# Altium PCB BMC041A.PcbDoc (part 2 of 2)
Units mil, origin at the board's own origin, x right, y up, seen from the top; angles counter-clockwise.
Board outline 3850 x 3650 mil, 6 copper layers (Top Layer, MidLayer1, MidLayer2, MidLayer3, MidLayer4, Bottom Layer), stack 62.8 mil thick; 106 components, 43 nets, 241 pads, 352 vias.
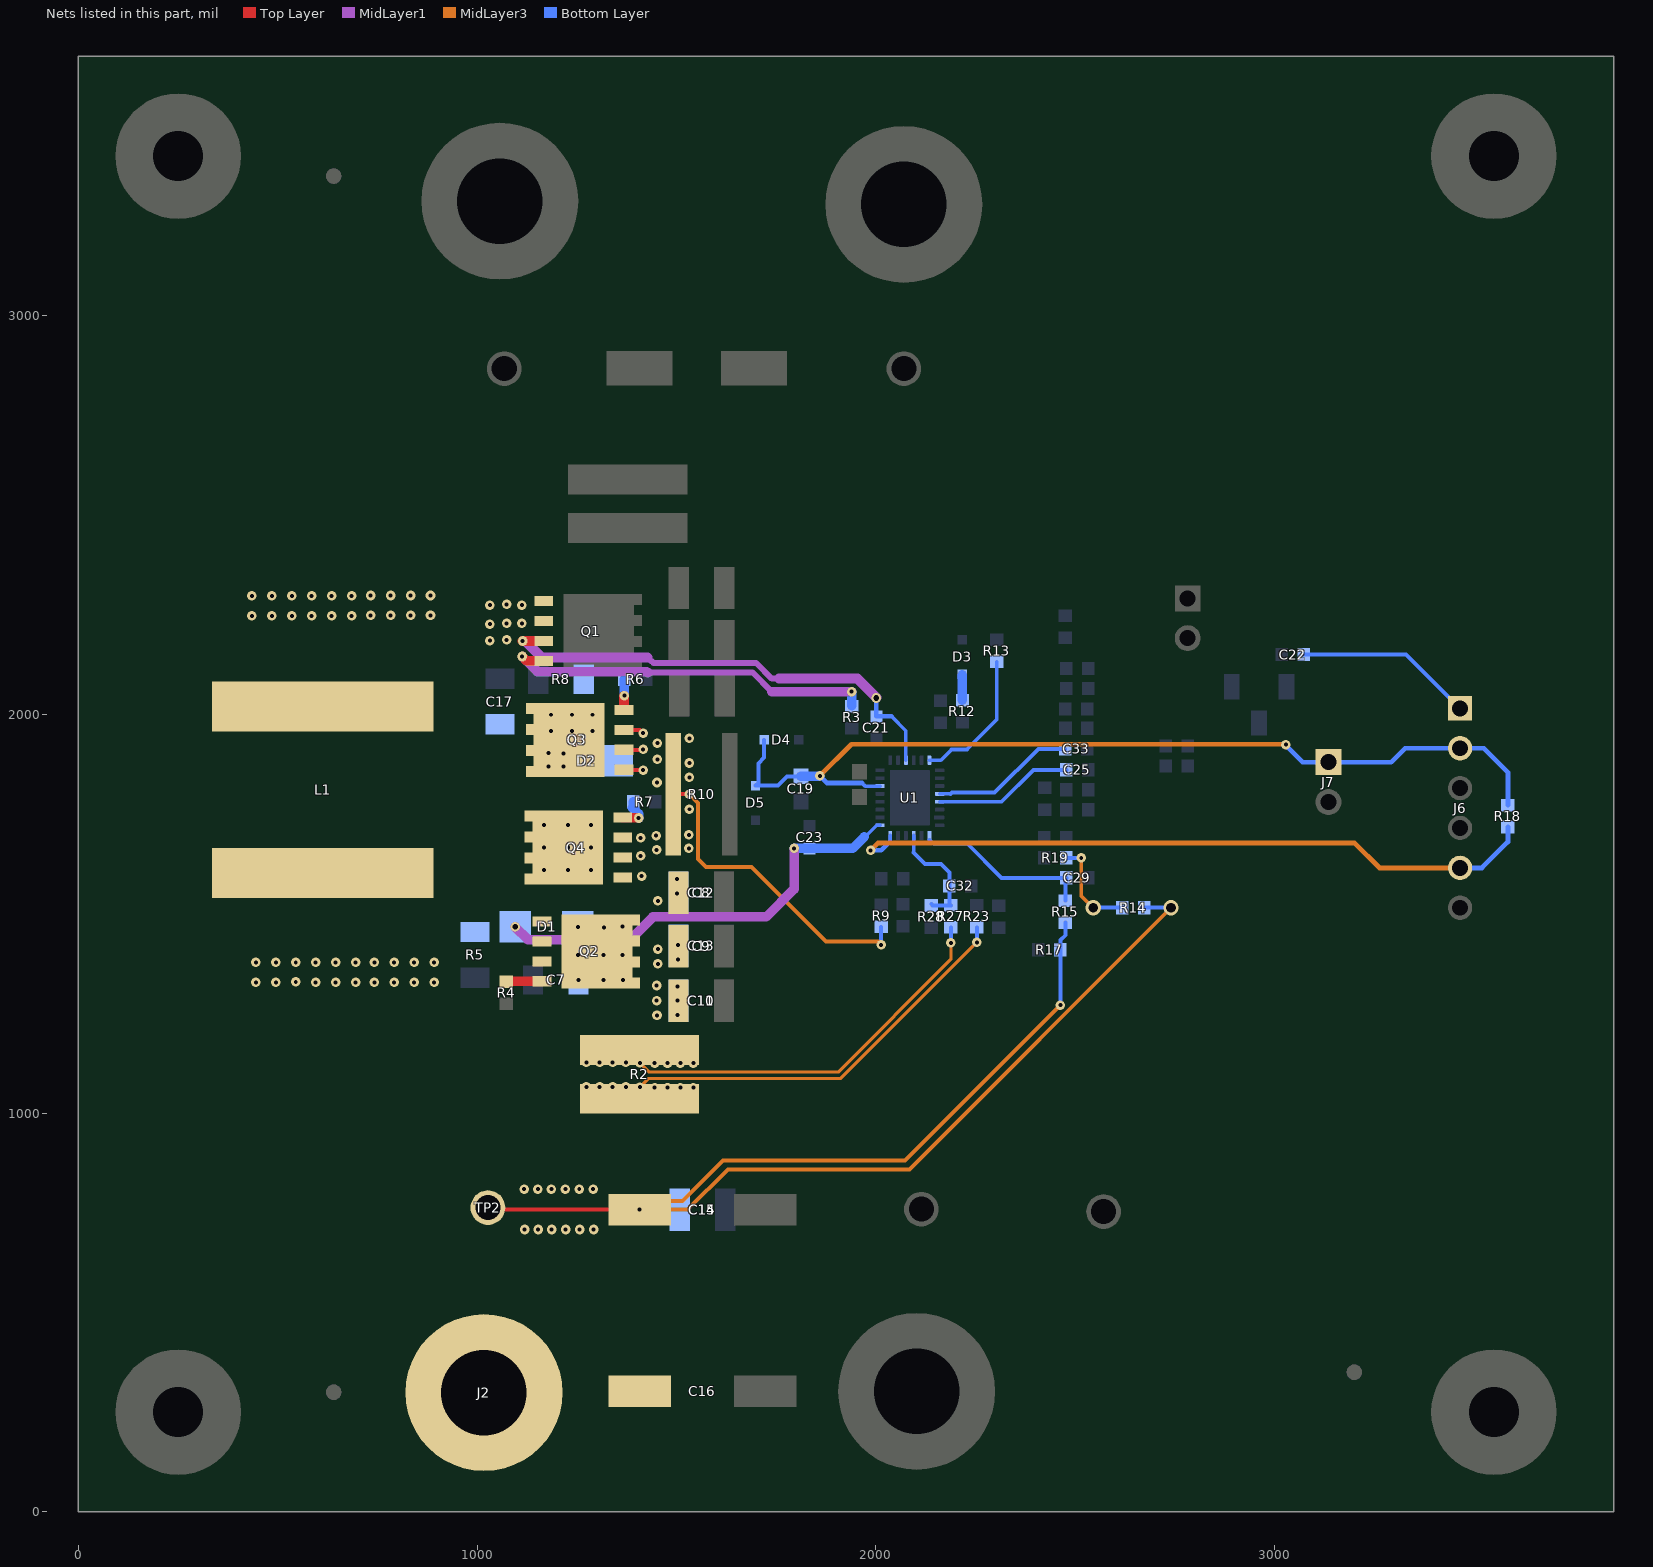
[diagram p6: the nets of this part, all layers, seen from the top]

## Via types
v1: diameter 24, hole 10, Top Layer to Bottom Layer, tented both sides, 212 vias
v2: diameter 24, hole 10, Top Layer to Bottom Layer, 124 vias
v3: diameter 19.68, hole 7.87, Top Layer to Bottom Layer, 9 vias
v4: diameter 24, hole 14, Top Layer to Bottom Layer, 3 vias
v5: diameter 38, hole 24, Top Layer to Bottom Layer, 2 vias
v6: diameter 24, hole 14, Top Layer to Bottom Layer, tented both sides, 2 vias

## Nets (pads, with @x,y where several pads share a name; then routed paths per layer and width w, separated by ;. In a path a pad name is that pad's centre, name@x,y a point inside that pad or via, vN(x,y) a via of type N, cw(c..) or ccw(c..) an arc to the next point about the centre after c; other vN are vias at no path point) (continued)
NetC32_2: C32.2 R27.1 R28.1 U1.11 | length 287.2
  Bottom Layer w9: 2094.84,1653.16 U1.11@2094.84,1696.14
  Bottom Layer w10: 2094.84,1653.16 2123.71,1624.29 2163,1624.29 2184.44,1602.85 C32.2@2184.44,1569.7 2184.44,1524.55 R27.1@2188,1520.99 2142.51,1520.99 R28.1@2139,1524.5
NetD2_2: D2.2 Q3.1 Q3.2 Q3.3 Q4.1 Q4.2 Q4.3 R8.1 R9.2 R10.2 | length 966.6
  Top Layer w10: Q3.1@1368.22,1861 1423,1861 v1@1424,1860 ; Q3.2@1368.22,1911 v1@1422,1911 ; Q3.3@1368.22,1961 1408,1961 v1(1416,1953) ; R10.2@1491.83,1800 v1(1532,1800)
  MidLayer3 w10: v1(1532,1800) 1554,1778 1554,1636.72 1573.6,1617.13 1687.87,1617.13 1875,1430 2005,1430 v1(2013,1422)
  Bottom Layer w10: v1(2013,1422) R9.2@2013,1467
  other v1: 1412.24,1594.33 1410,1645 1450,1660 1531,1664 1410,1690 1449,1696 1531,1698 1532,1762 1451,1829 1532,1842 1416,1860 1532,1878 1452,1887 1416,1912 1452,1928 1532,1940
NetD3_1: D3.1 R12.2 | length 64.1
  Bottom Layer w24: R12.2@2217,2035.56 D3.1@2217,2099.71
NetQ1_4: Q1.4 R3.1 | length 956.5
  Top Layer w24: v1(1113,2145) 1124,2134 Q1.4@1166.78,2134
  MidLayer1 w15: 1427.35,2105 1449.29,2105 1449.66,2105.37 1472.34,2105.37 1472.71,2105 1691,2105 1739,2057
  MidLayer1 w24: v1(1113,2145) 1151,2107 1425.35,2107 1427.35,2105 ; 1739,2057 v2(1939,2057)
  Bottom Layer w24: R3.1@1939,2021.56 v2(1939,2057)
NetQ2_4: Q2.4 R4.1 | length 90.2
  Top Layer w24: R4.1@1073,1329.56 1073.94,1330.5 Q2.4@1162.78,1330.5
NetQ3_4: Q3.4 R6.1 | length 77.6
  Top Layer w24: Q3.4@1368.22,2011 1368.22,2046.22 v2(1369,2047)
  Bottom Layer w24: R6.1@1368.44,2088 1368.44,2047.56 v2(1369,2047)
NetQ4_4: Q4.4 R7.1 | length 80.8
  Top Layer w24: Q4.4@1365.22,1741 v1@1404,1741
  Bottom Layer w24: R7.1@1389.3,1765.8 1391.44,1767.93 R7.1@1391.44,1781 ; 1393.73,1761.27 1405,1750 v1(1405,1740)
NetR13_1: R13.1 U1.28 | length 355.7
  Bottom Layer w9: U1.28@2134,1885.33 U1.28@2134.21,1885.12 2163.12,1885.12 2190,1912 ; 2228,1912 2303,1987 R13.1@2303,2131.44
  Bottom Layer w10: 2190,1912 2228,1912
NetR14_2: R14.2 R19.2 | length 228.2
  MidLayer3 w10: v1(2515,1640) 2515,1545 v5@2535,1525
  Bottom Layer w10: R19.2@2477.56,1640 v1(2515,1640) ; v5(2545,1515) R14.2@2612.44,1515
PGOOD: J6.5 R18.1 U1.14 | length 1768.3
  MidLayer3 w12: v1(1987,1659) 2005,1677 3201,1677 3263,1615 J6.5@3465,1615
  Bottom Layer w9: 2035.79,1681.42 U1.14@2035.79,1696.14
  Bottom Layer w12: v1(1987,1659) 2013.37,1659 2035.79,1681.42 ; J6.5@3465,1615 3520,1615 3585,1680 R18.1@3585,1717.44
SLOPE: C33.1 U1.4 | length 361.6
  Bottom Layer w9: U1.4@2159.8,1800.47 2187.47,1800.47
  Bottom Layer w10: 2187.47,1800.47 2190.43,1803.43 2197.2,1803.43 2297.8,1803.43 2407.8,1913.43 C33.1@2474.64,1913.43
SS: C25.1 U1.5 | length 350.7
  Bottom Layer w9: U1.5@2159.8,1780.79 2315.16,1780.79
  Bottom Layer w10: 2315.16,1780.79 2395,1860.63 C25.1@2477.44,1860.63
SW1: C17.1 C21.1 D2.1 L1.1 Q1.1 Q1.2 Q1.3 Q3.5 Q3.6 Q3.7 Q3.8 Q3.9 U1.25 | length 1202.1
  Top Layer w25: v1(1114,2184) Q1.3@1166.78,2184
  MidLayer1 w12: v4(2001,2041) v4@2001,2042
  MidLayer1 w15: 1427,2143 1435.63,2134.37 1436.69,2134.37 1442.19,2128.87 1699.47,2128.87 1738.97,2089.37 1757.41,2089.37
  MidLayer1 w25: v1@1120.32,2184 1161.32,2143 1427,2143 ; 1757.41,2089.37 1953.63,2089.37 v4@2001,2042
  Bottom Layer w9: 2039,1995 2075.16,1958.84 2075.16,1924.84 2075.16,1900.32 U1.25@2075.16,1885.12
  Bottom Layer w12: v4(2001,2041) C21.1@2001,1995 2039,1995
  other v1: 1032,2185 1074,2187 1032,2226 1074,2228 1112,2228 435,2247 485,2247 535,2247 585,2247 635,2247 685,2247 733,2248 783,2248 833,2248 883,2248 1032,2274 1112,2274 1074,2276 435,2297 485,2297 535,2297 585,2297 635,2297 685,2297 733,2298 783,2298 833,2298 883,2298
  other v2: 1179,1869 1216,1869 1216,1902 1179,1903 1185,1958 1238,1958 1289,1958 1185,1999 1238,1999 1289,1999
SW2: C23.2 D1.2 L1.2 Q2.1 Q2.2 Q2.3 Q4.5 Q4.6 Q4.7 Q4.8 Q4.9 R5.1 U1.15 | length 1107.4
  MidLayer1 w24: v6(1095.26,1467) 1127.13,1435.13 1271,1435.13 1272,1434.13 1331.2,1434.13 1332.2,1435.13 1384.05,1435.13 1440.92,1492 1725,1492 1795,1562 v1(1795,1664)
  Bottom Layer w9: 1971,1693 1973,1693 2001.73,1721.73 U1.15@2010.2,1721.73
  Bottom Layer w24: v1(1795,1664) C23.2@1834,1664 1942,1664 1971,1693
  other v1: 445,1328 495,1328 595,1328 645,1328 695,1328 742,1328 792,1328 842,1328 892,1328 545,1329 445,1378 495,1378 545,1378 595,1378 645,1378 695,1378 742,1378 792,1378 842,1378 892,1378
  other v2: 1168,1610 1227.5,1610 1285,1610 1168,1666 1227.5,1666 1285,1666 1168,1722 1227.5,1722 1285,1722
SYNC: C22.1 J6.1 | length 448.4
  Bottom Layer w10: C22.1@3072.56,2150 3330,2150 J6.1@3465,2015
VCC: C19.2 D4.2 D5.2 J6.2 J7.1 R18.2 U1.20 | length 2356.6
  MidLayer3 w12: v1(1859.41,1845.59) 1938.82,1925 3027,1925 v1(3028,1924)
  Bottom Layer w9: 1964.89,1828.13 1972.86,1820.16 U1.20@2010.2,1820.16
  Bottom Layer w10: D4.2@1719.69,1936 1719.69,1891.69 1705,1877 1705,1828.31 D5.2@1698,1821.31 1754.31,1821.31 1777.5,1844.5 C19.2@1812,1844.5
  Bottom Layer w12: v1(1859.41,1845.59) 1876.87,1828.13 1964.89,1828.13 ; v1(3028,1924) 3027.9,1923.9 3027.9,1922.1 3070,1880 3292,1880 3327,1915 J6.2@3465,1915 3525,1915 3585,1855 R18.2@3585,1772.56
  Bottom Layer w24: C19.2@1812,1844.5 1858.31,1844.5 v1(1859.41,1845.59)
VOSNS: C29.1 R15.2 U1.9 | length 437.7
  Bottom Layer w10: U1.9@2134.21,1685.21 2143.95,1675.47 2229.53,1675.47 2315,1590 C29.1@2477.44,1590 ; R15.2@2475,1532.56 C29.1@2475,1587.56
VOSNS+: C7.1 C8.1 C9.1 C10.1 C11.1 C12.1 C13.1 D1.1 Q2.5 Q2.6 Q2.7 Q2.8 Q2.9 R2.1 R27.2 | length 1057.8
  Top Layer w10: R2.1@1406,1130 R2.1@1407,1131 ; R2.1@1407,1124 R2.1@1407,1131 ; R2.1@1407,1167.87 R2.1@1407,1158.02 R2.1@1407,1131
  MidLayer3 w8: v2(1408,1126) 1431.13,1102.87 1905.42,1102.87 2188,1385.45 v1(2188,1427)
  Bottom Layer w10: C12.1@1493.88,1544.12 C12.1@1499.88,1550.12 ; C11.1@1495.88,1275.12 C11.1@1501.88,1281.12 ; C13.1@1496.88,1414.12 C13.1@1502.88,1420.12 ; v1(2188,1427) R27.2@2188,1465.87
  other v2: 1445,1125 1477.33,1125 1509.67,1125 1542,1125 1274,1127 1307,1127 1340,1127 1373,1127 1451,1245 1502.88,1246.24 1450,1282 1502.88,1282.12 1502.88,1318 1450,1320 1254.09,1334 1317,1334 1366,1334 1453,1374 1503.88,1385.24 1253,1397 1317,1397 1365,1397 1453,1411 1503.88,1421.12 1318,1466 1252.74,1467 1365,1468 1453,1532 1500.88,1551.12 1500.88,1587
VOSNS-: C14.1 C15.1 C16.1 J2.1 R2.2 R14.1 R15.1 R17.1 R23.2 TP2.1 | length 4652.5
  Top Layer w8: R2.2@1407,1026.13 R2.2@1407,1035.98 1407,1064 v2(1408,1065)
  Top Layer w10: TP2.1@1027,763 1032,758 v2(1407.52,758)
  MidLayer3 w8: v2(1408,1065) 1430,1087 1912,1087 v1(2253,1428)
  MidLayer3 w10: v1(2462.56,1270.56) 2073,881 1616,881 1515,780 1429.52,780 v2(1407.52,758) 1528,758 1629,859 2084,859 v5(2740,1515)
  Bottom Layer w10: v1(2253,1428) R23.2@2253,1465.87 ; v1(2462.56,1270.56) R17.1@2462.56,1410 2462.56,1433.56 2475,1446 R15.1@2475,1477.44 ; R14.1@2668.05,1515 R14.1@2672.56,1515 v5(2740,1515)
  other v1: 1119,708 1153,708 1187,708 1222,708 1257,708 1292,708 1118,809 1152,809 1186,809 1221,809 1256,809 1291,809
  other v2: 1445,1064 1477.33,1064 1509.67,1064 1542,1064 1274,1066 1307,1066 1340,1066 1373,1066
pads on no net: FID1.1 FID2.1 FID3.1 FID4.1 FID5.1 FID6.1 H1.1 H2.1 H3.1 H4.1 H5.0 H6.0 H7.0 H8.0 S1.3 U1.29@2058.82,1756.57 U1.29@2058.82,1824.69 U1.29@2111.18,1756.57 U1.29@2111.18,1824.69

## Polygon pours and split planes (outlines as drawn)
GND on MidLayer3 "Top Layer-No Net 6" (solid, remove dead copper, pour order 92): 15,15 15,3625 3825,3625 3825,15
GND on MidLayer4 "Top Layer-No Net" (solid, remove dead copper, pour order 100): 3579,3638 1574,3638 1574,16 3839.34,16 3836.43,3531.49 3836.43,3638
GND on MidLayer4 "Top Layer-No Net 6" (solid, remove dead copper, pour order 101): 20,20 20,3630 3830,3630 3830,20
INSNS+ on MidLayer4 "Top Layer-No Net 7" (solid, remove dead copper, pour order 99): 1549,2537 1135,2537 13,2537 13,2679 13,2843 13,3019 13,3190 13,3349 13,3546 13,3640 1549,3640
INSNS- on MidLayer4 "Top Layer-No Net 9" (solid, remove dead copper, pour order 94): 1548,2387 1548,1993 1460,1993 1460,2059 1460,2062 1415,2107 1208,2107 1208,2365 11,2365 11,2514 1208,2514 1548,2514
SW1 on MidLayer4 "Top Layer-No Net 4" (solid, remove dead copper, pour order 97): 1321,1836 1321,2032 1190.31,2032 1190.31,2344 397,2344 397,1949 956,1949 1069,1836
SW2 on MidLayer4 "Top Layer-No Net 3" (solid, remove dead copper, pour order 96): 1014,1295 394.41,1295 394.41,1680 959.41,1680 1049.41,1770 1326.07,1770 1326.07,1567.86 1188.41,1567.86 1188.41,1361 1036.41,1361 1036.41,1295
VOSNS+ on MidLayer4 "Top Layer-No Net 8" (solid, remove dead copper, pour order 95): 1465,1606 1549.15,1606 1550,1605.15 1561.52,1593.63 1561.52,1174.72 1561.52,1105.02 1560.54,1104 1119,1104 17,1104 14,1107 14,1244 1141,1244 1203,1306 1203,1541 1270,1541 1340,1541 1415,1541 1465,1591
VOSNS- on MidLayer4 "Bottom Layer-No Net" (solid, remove dead copper, pour order 98): 1562,1087 1561,1086 1561,14 14,14 11,17 11,1082
NetD2_2 on MidLayer4 "Top Overlay-No Net" (solid, remove dead copper, pour order 93): 1341,1575 1418,1575 1438,1595 1438,1626.1 1552,1626.1 1552,1979.6 1499,1979.6 1440,1979.6 1440,2038.6 1401.4,2077.2 1341,2077.2
GND on MidLayer1 "Top Layer-No Net 6" (solid, remove dead copper, pour order 83): 20,20 20,3630 3830,3630 3830,20
GND on Bottom Layer "Top Layer-No Net" (solid, remove dead copper, pour order 110): 3814,3646 3809,3641 1551,3641 1551,19 3817,19
VOSNS- on Bottom Layer "Bottom Layer-No Net" (solid, remove dead copper, pour order 108): 1562,1085 1561,1084 1561,12 14,12 11,15 11,1080
VOSNS+ on Bottom Layer "Top Layer-No Net 8" (solid, remove dead copper, pour order 105): 1464,1607 1548.15,1607 1549,1606.15 1560.52,1594.63 1560.52,1175.72 1560.52,1106.02 1559.54,1105 1118,1105 16,1105 13,1108 13,1245 1140,1245 1202,1307 1202,1542 1269,1542 1339,1542 1414,1542 1464,1592
SW2 on Bottom Layer "Top Layer-No Net 3" (solid, remove dead copper, pour order 106): 1014,1295 394.41,1295 394.41,1680 959.41,1680 1049.41,1770 1326.07,1770 1326.07,1567.86 1188.41,1567.86 1188.41,1361 1036.41,1361 1036.41,1295
SW1 on Bottom Layer "Top Layer-No Net 4" (solid, remove dead copper, pour order 107): 1309,1838 1309,2034 1186.31,2034 1186.31,2346 393,2346 393,1951 952,1951 1065,1838
NetD2_2 on Bottom Layer "Top Overlay-No Net" (solid, remove dead copper, pour order 102): 1322,1575 1418,1575 1438,1595 1438,1626.1 1552,1626.1 1552,1979.6 1499,1979.6 1440,1979.6 1440,2038.6 1420.6,2058 1343.8,2134.8 1237,2134.8 1237,2047.35 1237,2046 1264.59,2046 1322,2046
INSNS- on Bottom Layer "Top Layer-No Net 9" (solid, remove dead copper, pour order 104): 1548,2387 1548,1993 1445,1993 1445,2074 1366,2153 1208,2153 1208,2365 11,2365 11,2514 1208,2514 1548,2514
INSNS+ on Bottom Layer "Top Layer-No Net 7" (solid, remove dead copper, pour order 109): 1547,2536 1135,2536 13,2536 13,2678 13,2842 13,3018 13,3189 13,3348 13,3545 13,3639 1547,3639
AGND on Bottom Layer "Bottom Layer-No Net 1" (solid, remove dead copper, pour order 103): 2498.67,2229.21 2923,2228.83 2923,1558 2500.1,1558
GND on Top Layer "Top Layer-No Net" (solid, remove dead copper, pour order 82): 3837,3644 3832,3639 1574,3639 1574,17 3840,17
INSNS- on Top Layer "Top Layer-No Net 9" (solid, remove dead copper, pour order 76): 1548,2387 1548,1993 1460,1993 1460,2059 1460,2062 1415,2107 1208,2107 1208,2365 11,2365 11,2514 1208,2514 1548,2514
VOSNS+ on Top Layer "Top Layer-No Net 8" (solid, remove dead copper, pour order 77): 1464,1607 1548.15,1607 1549,1606.15 1560.52,1594.63 1560.52,1175.72 1560.52,1106.02 1559.54,1105 1118,1105 16,1105 13,1108 13,1245 1140,1245 1202,1307 1202,1542 1269,1542 1339,1542 1414,1542 1464,1592
VOSNS- on Top Layer "Bottom Layer-No Net" (solid, remove dead copper, pour order 80): 1562,1088 1561,1087 1561,15 14,15 11,18 11,1083
SW1 on Top Layer "Top Layer-No Net 4" (solid, remove dead copper, pour order 79): 1321,1836 1321,2032 1190.31,2032 1190.31,2344 432,2344 316,2228 316,1949 956,1949 1069,1836
SW2 on Top Layer "Top Layer-No Net 3" (solid, remove dead copper, pour order 78): 1014.59,1295 426,1295 318,1403 318,1680 960,1680 1050,1770 1326.67,1770 1326.67,1567.86 1189,1567.86 1189,1361 1037,1361 1037,1295
NetD2_2 on Top Layer "Top Overlay-No Net" (solid, remove dead copper, pour order 75): 1341,1575 1418,1575 1438,1595 1438,1626.1 1552,1626.1 1552,1979.6 1499,1979.6 1440,1979.6 1440,2038.6 1401.4,2077.2 1341,2077.2
INSNS+ on Top Layer "Top Layer-No Net 7" (solid, remove dead copper, pour order 81): 1537.69,2540 2.69,2540 2.69,2687.48 2.69,2851.48 2.69,3027.48 2.69,3198.48 2.69,3357.48 2.69,3554.48 2.69,3648.48 1537.69,3648.48
GND on MidLayer2 "Top Layer-No Net" (solid, remove dead copper, pour order 91): 3837.01,3637.7 1574,3637.7 1574,15.7 3840,15.7 3837.01,3635.93
INSNS+ on MidLayer2 "Top Layer-No Net 7" (solid, remove dead copper, pour order 90): 1549,2537 1135,2537 13,2537 13,2679 13,2843 13,3019 13,3190 13,3349 13,3546 13,3640 1549,3640
INSNS- on MidLayer2 "Top Layer-No Net 9" (solid, remove dead copper, pour order 85): 1549,2387 1549,1993 1461,1993 1461,2059 1461,2062 1416,2107 1209,2107 1209,2365 12,2365 12,2514 1209,2514 1549,2514
NetD2_2 on MidLayer2 "Top Overlay-No Net" (solid, remove dead copper, pour order 84): 1341,1575 1418,1575 1438,1595 1438,1626.1 1552,1626.1 1552,1979.6 1499,1979.6 1440,1979.6 1440,2038.6 1401.4,2077.2 1341,2077.2
VOSNS+ on MidLayer2 "Top Layer-No Net 8" (solid, remove dead copper, pour order 86): 1464,1607 1548.15,1607 1549,1606.15 1560.52,1594.63 1560.52,1175.72 1560.52,1106.02 1559.54,1105 1118,1105 16,1105 13,1108 13,1245 1140,1245 1202,1307 1202,1542 1269,1542 1339,1542 1414,1542 1464,1592
VOSNS- on MidLayer2 "Bottom Layer-No Net" (solid, remove dead copper, pour order 89): 1563,1088 1562,1087 1562,15 15,15 12,18 12,1083
SW1 on MidLayer2 "Top Layer-No Net 4" (solid, remove dead copper, pour order 88): 1321,1836 1321,2032 1190.31,2032 1190.31,2344 397,2344 397,1949 956,1949 1069,1836
SW2 on MidLayer2 "Top Layer-No Net 3" (solid, remove dead copper, pour order 87): 1015,1295 395.41,1295 395.41,1680 960.41,1680 1050.41,1770 1327.07,1770 1327.07,1567.86 1189.41,1567.86 1189.41,1361 1037.41,1361 1037.41,1295

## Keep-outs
Keep-Out Layer:
  lines w7: -3.5,0 ccw(c0,0) 0,-3.5 ; -3.5,0 ccw(c0,0) 0,-3.5 ; -3.5,0 -3.5,3650 ; -3.5,3650 cw(c0,3650) 0,3653.5 ; -3.5,3650 cw(c0,3650) 0,3653.5 ; 0,-3.5 3850,-3.5 ; 0,3653.5 3850,3653.5 ; 3850,-3.5 ccw(c3850,0) 3853.5,0 ; 3850,-3.5 ccw(c3850,0) 3853.5,0 ; 3850,3653.5 cw(c3850,3650) 3853.5,3650 ; 3850,3653.5 cw(c3850,3650) 3853.5,3650 ; 3853.5,0 3853.5,3650
  text ".Layer_Name" at 577,-858.49 h60

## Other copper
Top Layer:
  pour cut-out: 2050.36,1443.05 2078.13,1443.05 2086,1435.18 2086,1400.82 2079.8,1394.53 2050.36,1394.53
  pour cut-out: 1635,1775 1585,1775 1580,1770 1575,1765.64 1562.77,1765.64 1555,1775 1495,1775 1495,1825 1496,1824 1555,1825 1562.76,1831.07 1575.01,1831.08 1582.08,1824 1635,1824
  text ".Layer_Name" at 577,-858.49 h60
MidLayer1:
  pour cut-out: 2050.28,1447.52 2078.05,1447.52 2085.92,1439.65 2085.92,1405.29 2079.72,1399 2050.28,1399
  pour cut-out: 1514.4,1826.23 1542.17,1826.23 1550.04,1818.36 1550.04,1784 1542.38,1776.23 1514.4,1776.23
  pour cut-out: 1574.36,1825.53 1602.13,1825.53 1610,1817.66 1610,1783.3 1602.34,1775.53 1574.36,1775.53
  text ".layer_Name" at 575,-860 h60
MidLayer2:
  pour cut-out: 1397,2486.42 1397,2577.58 1391.38,2583.2 1366.77,2583.2 1360.47,2576.89 1360.47,2486.03 1368.42,2478.08 1388.66,2478.08
  pour cut-out: 1427.23,1050.23 1427.23,1141.38 1421.61,1147 1397,1147 1390.7,1140.7 1390.7,1049.83 1398.65,1041.88 1418.88,1041.88
  pour cut-out: 2049.36,1445.05 2077.13,1445.05 2085,1437.18 2085,1402.82 2078.8,1396.53 2049.36,1396.53
  pour cut-out: 1515.36,1826.53 1543.13,1826.53 1551,1818.66 1551,1784.3 1543.34,1776.53 1515.36,1776.53
  pour cut-out: 1574.36,1825.53 1602.13,1825.53 1610,1817.66 1610,1783.3 1602.34,1775.53 1574.36,1775.53
  text ".layer_Name" at 575,-860 h60
MidLayer3:
  pour cut-out: 2050.28,1446.52 2078.05,1446.52 2085.92,1438.65 2085.92,1404.29 2079.72,1398 2050.28,1398
  pour cut-out: 1514.36,1825.47 1542.13,1825.47 1550,1817.6 1550,1783.24 1542.34,1775.47 1514.36,1775.47
  pour cut-out: 1574.36,1824.47 1602.13,1824.47 1610,1816.6 1610,1782.24 1602.34,1774.47 1574.36,1774.47
  text ".layer_Name" at 575,-860 h60
MidLayer4:
  pour cut-out: 1427.17,1050.17 1427.17,1141.33 1421.55,1146.95 1396.95,1146.95 1390.64,1140.64 1390.64,1049.78 1398.6,1041.83 1418.83,1041.83
  pour cut-out: 1396,2482.42 1396,2573.58 1390.38,2579.2 1365.77,2579.2 1359.47,2572.89 1359.47,2482.03 1367.42,2474.08 1387.66,2474.08
  pour cut-out: 2050.36,1445.05 2078.13,1445.05 2086,1437.18 2086,1402.82 2079.8,1396.53 2050.36,1396.53
  pour cut-out: 1552,1780 1522,1780 1512,1790 1512,1810 1522,1820 1552,1820
  pour cut-out: 1574.36,1824.47 1602.13,1824.47 1610,1816.6 1610,1782.24 1603.85,1776 1574.36,1776
  text ".layer_Name" at 575,-860 h60
Bottom Layer:
  pour cut-out: 1396.53,2479.96 1396.53,2571.11 1390.91,2576.73 1366.3,2576.73 1360,2570.43 1360,2479.57 1367.95,2471.62 1388.18,2471.62
  pour cut-out: 1427.23,1050.23 1427.23,1141.38 1421.61,1147 1397,1147 1390.7,1140.7 1390.7,1049.83 1398.65,1041.88 1418.88,1041.88
  pour cut-out: 2040,1496 2108.3,1496 2108.3,1425.01 2079.43,1395.74 2040,1395.74
  pour cut-out: 1574.36,1824.52 1602.13,1824.52 1610,1816.65 1610,1782.29 1603.8,1776 1574.36,1776
  pour cut-out: 1551,1780 1521,1780 1511,1790 1511,1810 1521,1820 1551,1820
  text ".Layer_Name" at 577,-858.49 h60

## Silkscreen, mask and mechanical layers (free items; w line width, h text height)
Top Overlay:
  text "6-24VDC" at 1321,3459 h70
  text "-" at 1770,3300 h100
  text "+" at 1315,3285 h100
  text "VIN" at 1484,3220 h70
  text "VIN" at 1015,2975 h40
  text "GND" at 2003,2971 h40
  text "LM34936EVM" at 2810,2815 h72.83
  text "EN" at 2761,2480 h40
  text "SYNC" at 3560,2005 h40
  text "VCC" at 3555,1910 h40
  text "MODE" at 3556.27,1800.31 h40
  text "COMP" at 3556.27,1693.56 h40
  text "DITHER" at 3020,1665 h40
  text "PGOOD" at 3555,1590 h40
  text "GND" at 3550,1495 h72.83
  text "VOUT" at 955,625 h40
  text "GND" at 2065,625 h40
  text "BIAS" at 2500,620 h40
  text "12VDC @ 6A" at 120,520 h70
  text "VOUT" at 535,415 h70
  text "-" at 2340,170 h100
  text "+" at 740,160 h100
  text ".Layer_Name" at 577,-858.49 h60
Bottom Overlay:
  pour cut-out: 2108.3,1497 2108.3,1436.39 2044.61,1436.39 2044,1437 2044.38,1437.38 2044.38,1497
  text "DITH" at 3240,1990 h40
  text ".Layer_Name" at 577,-858.49 h60
Top Paste:
  text ".Layer_Name" at 577,-858.49 h60
Bottom Paste:
  text ".Layer_Name" at 577,-858.49 h60
Top Solder:
  text ".Layer_Name" at 577,-858.49 h60
  text ".Layer_Name" at 577,-858.49 h60
Bottom Solder:
  text ".Layer_Name" at 577,-858.49 h60
Drill Guide:
  text ".Layer_Name" at 577,-858.49 h60
M1 Board Outline:
  the board outline again, w8
  text ".Layer_Name" at 577,-858.49 h60
M2 Board Dimensions:
  rectangle: 125,-410.5 500,-285.5
  rectangle: 0,-285.5 125,-160.5
  lines w7: 0,-285.5 1000,-285.5 ; 125,-410.5 125,-160.5 ; 250,-410.5 250,-160.5 ; 500,-410.5 500,-160.5 ; 750,-410.5 750,-160.5 ; 0,-410.5 0,-160.5 1000,-160.5 1000,-410.5 0,-410.5
  text ".Layer_Name" at 577,-858.49 h60
M3 3D STEP Top:
  text ".Layer_Name" at 577,-858.49 h60
M4 3D STEP Bottom:
  text ".Layer_Name" at 577,-858.49 h60
M5 Assembly Top:
  lines w10: -292,-930.17 6308,-930.17 ; -292,-726.83 6310,-726.83 ; -292,-523.5 -292,-1133.5 3713,-1133.5 6310,-1133.5 6310,-523.5 -291.5,-523.5 -291.5,-1133.5 1284,-1133.5 ; 2173,-1133.5 2173,-523.5 ; 3440,-726.83 3440,-523.5 ; 4280,-726.83 4280,-523.5 ; 4902,-1140 4902,-937.17
  text "COMPONENTS MARKED 'DNP' SHOULD NOT BE POPULATED." at 1153.5,-318.5 h60
  text "ASSEMBLY VARIANT:" at 1153,-434 h60
  text ".VariantName" at 2189,-434 h60
  text "PCB VIEWED FROM TOP SIDE" at -228.5,-655.67 h60
  text "BOARD #:" at 2248,-655.67 h60
  text ".PRJ_Number" at 2793.5,-655.67 h60
  text "REV:" at 3638,-655.67 h60
  text ".PCB_Rev" at 3929.5,-655.67 h60
  text "SVN REV:" at 4476,-655.67 h60
  text ".VersionControl_RevNumber" at 4982,-655.67 h60
  text "IGNORE ->" at -228.5,-858.49 h60
  text "PLOT NAME =" at -228.5,-1064.34 h60
  text ".plot_File_Name" at 577,-1064.34 h60
  text "GENERATED    :" at 2250,-1064.34 h60
  text ".Print_Date" at 3119.5,-1064.34 h60
  text ".Print_Time" at 3848.5,-1064.34 h60
  text "TEXAS INSTRUMENTS" at 5113,-1064.34 h60
M6 Assembly Bottom:
  lines w10: -292.5,-727.33 6309.5,-727.33 ; -290.5,-930.67 6309.5,-930.67 ; 1115.5,-1140.5 1115.5,-937.67 ; 1737.5,-727.33 1737.5,-524 ; 2577.5,-727.33 2577.5,-524 ; 3844.5,-1134 3844.5,-524 ; 4733.5,-1134 6309,-1134 6309,-524 -292.5,-524 -292.5,-1134 2304.5,-1134 6309.5,-1134 6309.5,-524
  text "COMPONENTS MARKED 'DNP' SHOULD NOT BE POPULATED." at 6102,-318 h60
  text ".VariantName" at 5058,-434 h60
  text "ASSEMBLY VARIANT:" at 6097,-434 h60
  text ".VersionControl_RevNumber" at 1035.5,-656.17 h60
  text "SVN REV:" at 1541.5,-656.17 h60
  text ".PCB_Rev" at 2088,-656.17 h60
  text "REV:" at 2379.5,-656.17 h60
  text ".PRJ_Number" at 3224,-656.17 h60
  text "BOARD #:" at 3769.5,-656.17 h60
  text "PCB VIEWED FROM BOTTOM SIDE" at 6246,-656.17 h60
  text "IGNORE ->" at 2547.85,-858.49 h60
  text "TEXAS INSTRUMENTS" at 904.5,-1064.84 h60
  text ".Print_Time" at 2169,-1064.84 h60
  text ".Print_Date" at 2898,-1064.84 h60
  text "GENERATED    :" at 3767.5,-1064.84 h60
  text ".plot_File_Name" at 5440.5,-1064.84 h60
  text "PLOT NAME =" at 6246,-1064.84 h60
M9 Title Sheet:
  lines w10: -491.5,1041.5 -291.5,1041.5 ; -491.5,3416.5 -291.5,3416.5 ; -491.5,5791.5 -291.5,5791.5 ; 2008.5,-1333.5 2008.5,-1133.5 ; 2008.5,7966.5 2008.5,8166.5 ; 4508.5,-1333.5 4508.5,-1133.5 ; 4508.5,7966.5 4508.5,8166.5 ; 6321,-1133.5 6321,-523.5 11303.5,-523.5 ; 7008.5,-1333.5 7008.5,-1133.5 ; 7008.5,7966.5 7008.5,8166.5 ; 9508.5,-1333.5 9508.5,-1133.5 ; 9508.5,7966.5 9508.5,8166.5 ; 11303.5,-1133.5 11303.5,-523.5 ; 11303.5,-823.5 14303.5,-823.5 ; 11303.5,-223.5 14303.5,-223.5 ; 11304.5,370.5 14304.5,370.5 ; 12008.5,-1333.5 12008.5,-1133.5 ; 12008.5,7966.5 12008.5,8166.5 ; 12808.5,-1123.5 12808.5,-523.5 ; 14303.5,-523.5 11303.5,-523.5 ; 14303.5,76.5 11303.5,76.5 ; 14308.5,66.5 14308.5,-1133.5 ; 14308.5,871 11304.5,871 11303.5,871 11303.5,370.5 11303.5,76.5 ; 14308.5,1041.5 14508.5,1041.5 ; 14308.5,3416.5 14508.5,3416.5 ; 14308.5,5791.5 14508.5,5791.5 ; 11303.5,-523.5 11303.5,76.5 ; 14308.5,-1133.5 -291.5,-1133.5 -291.5,7966.5 14308.5,7966.5 14308.5,-1133.5 ; -491.5,-1333.5 14508.5,-1333.5 14508.5,8166.5 -491.5,8166.5 -491.5,-1333.5
  text "1" at 739.84,8036.5 h70
  text "2" at 3235.5,8036.5 h70
  text "3" at 5724.84,8036.5 h70
  text "4" at 8231.51,8036.5 h70
  text "5" at 10730.5,8036.5 h70
  text "6" at 13235.5,8036.5 h70
  text "A" at -416.5,6893.5 h70
  text "A" at 14383.5,6893.5 h70
  text "B" at -416.5,4513.5 h70
  text "B" at 14383.5,4513.5 h70
  text "C" at -416.5,2138.5 h70
  text "C" at 14383.5,2138.5 h70
  text "PROJECT TITLE:" at 11343.5,277.5 h45
  text ".PRJ_Title" at 11393.5,144.17 h70
  text "DESIGNED FOR:" at 11343.5,-23.5 h45
  text ".PRJ_Customer" at 11393.5,-163.5 h70
  text "D" at -416.5,-231.5 h70
  text "D" at 14383.5,-231.5 h70
  text "FILE NAME:" at 11343.5,-323.5 h45
  text ".PCB_File_Name_No_Path" at 11393.5,-443.5 h70
  text "ENGINEER:" at 11343.5,-613.5 h45
  text "LAYOUT BY:" at 12848.5,-613.5 h45
  text ".PRJ_Engineer" at 11393.5,-768.49 h70
  text ".PCB_Layout" at 12899,-768.49 h70
  text ".Layer_Name" at 577,-858.49 h60
  text "ALTIUM DESIGNER VERSION:" at 12848.5,-923.5 h45
  text ".print_Scale" at 11393.5,-1056.83 h70
  text ".Application_BuildNumber" at 12899,-1056.83 h70
  text "1" at 739.84,-1263.5 h70
  text "2" at 3235.5,-1263.5 h70
  text "3" at 5724.84,-1263.5 h70
  text "4" at 8231.51,-1263.5 h70
  text "5" at 10730.5,-1263.5 h70
  text "6" at 13235.5,-1263.5 h70
M10 Fab Notes:
  drawing of 189 lines, arcs and shapes, not listed
  text "DESIGN INFORMATION" at 12377.02,6360.17 h60
  text "MIN. TRACK WIDTH:" at 11732.46,6228.05 h60
  text "8" at 12828.7,6228.05 h60
  text "MIL" at 12983.46,6228.05 h60
  text "MIN. CLEARANCE:" at 11732.46,6103.92 h60
  text "0.2" at 12768.7,6103.93 h60
  text "mm" at 12983.46,6103.92 h60
  text "MIN. VIA PAD SIZE:" at 11732.46,5979.8 h60
  text "24" at 12798.71,5979.8 h60
  text "MIL" at 12983.46,5979.8 h60
  text "0.05mm (2MIL)" at 12427.46,5849.9 h60
  text "MINIMUM ANNULAR RING" at 11403.23,5841.67 h60
  text "EXTERNAL" at 13135.46,5841.67 h60
  text "PER" at 11603.23,5731.55 h60
  text "IPC-D-275 CLASS 2 LEVEL C" at 11823.23,5731.54 h60
  text "MIL, HOLES" at 13311.46,5631.07 h60
  text "+/-" at 12919,5622.48 h60
  text "+/-" at 13773,5622.48 h60
  text "REGISTRATION TOLERANCES:" at 11403.23,5621.42 h60
  text "METAL" at 12603,5621.42 h60
  text "5" at 13179.2,5621.42 h60
  text "3" at 14012.2,5621.42 h60
  text "MIL" at 14128.46,5621.42 h60
  text "HOLE SIZE TOLERANCE (UNLESS OTHERWISE SPECIFIED):" at 11403.23,5523.1 h60
  text "+/-" at 13773,5520.23 h60
  text "3" at 14012.2,5519.17 h60
  text "MIL" at 14128.46,5519.17 h60
  text "MATERIAL:" at 11328.46,5381.52 h60
  text "FR-4 High Tg" at 12314.9,5253 h60
  text "X" at 12170.46,5245.01 h60
  text "FR-408" at 11749.46,5240.49 h60
  text "OTHER" at 13237.46,5240.49 h60
  text "62 MIL (1.6mm) +/-10%" at 12069.56,5097.46 h60
  text "X" at 11949.46,5095.01 h60
  text "THICKNESS:" at 11403.23,5089.24 h60
  text "OTHER" at 13354.46,5089.24 h60
  text "TOLERANCE:" at 11403.23,4950.92 h60
  text "X" at 12251.46,4950.92 h60
  text "ANSI IPC-6012 TYPE 3 CLASS 2" at 12429.48,4950.92 h60
  text "OTHER +/-" at 12429.46,4806.73 h60
  text "BOW & TWIST:" at 11403.23,4661.54 h60
  text "X" at 12251.46,4661.54 h60
  text "ANSI IPC-6012 TYPE 3 CLASS 2" at 12429.48,4661.54 h60
  text "OTHER +/-" at 12429.46,4514.85 h60
  text "DRILLING:" at 11328.46,4384.23 h60
  text "NC_DRILL FILES" at 13089.46,4279.04 h60
  text "REFERENCE:" at 11403.23,4275.1 h60
  text "X" at 12060.46,4275.01 h60
  text "AS SHOWN" at 12238.46,4275.1 h60
  text "X" at 12961.46,4275.1 h60
  text "OTHER" at 13387.46,4132.85 h60
  text "PTH COPPER THICKNESS:" at 11402.91,4129.32 h60
  text "X" at 12542.14,4129.32 h60
  text "20-30 um" at 12670.14,4129.32 h60
  text "BOARD FINISH:" at 11328.46,3981.73 h60
  text "SILKSCREEN:" at 11483.68,3871.6 h60
  text "X" at 12441.46,3871.6 h60
  text "TOP" at 12558.46,3871.6 h60
  text "X" at 12951.46,3871.6 h60
  text "BOTTOM" at 13069.46,3871.6 h60
  text "SILKSCREEN COLOR:" at 11483.68,3716.41 h60
  text "X" at 12440.46,3716.41 h60
  text "WHITE" at 12558.46,3716.41 h60
  text "OTHER" at 13069.46,3716.41 h60
  text "X" at 12571.46,3572.96 h60
  text "GREEN" at 12689.46,3572.96 h60
  text "OTHER" at 13307.46,3572.96 h60
  text "SOLDER RESIST COLOR:" at 11483.68,3566.1 h60
  text "X" at 12571.46,3418.71 h60
  text "MATTE" at 12689.46,3418.71 h60
  text "SEMI-GLOSS" at 13307,3418.07 h60
  text "IMMERSION GOLD (ENIG)" at 12389.46,3245.94 h60
  text "ENEPIG" at 13727,3238.72 h60
  text "SURFACE FINISH:" at 11328.46,3237.72 h60
  text "X" at 12211.46,3237.72 h60
  text "IMM. TIN/SILVER OR EQUIV" at 11658,3100.4 h60
  text "OTHER" at 13089.46,3096.47 h60
  text "ARRAY/PANEL:" at 11328.46,2941.09 h60
  text "CUT AND TRIM PER M1 BOARD OUTLINE" at 12389.46,2932.87 h60
  text "N.C. ROUTE" at 12389.46,2796.9 h60
  text "X" at 13077.46,2796.9 h60
  text "V. SCORE" at 13255.46,2796.9 h60
  text "CERTIFICATION:" at 11328.46,2667.77 h60
  text "MATERIALS AND WORKMANSHIP FOR ALL PCBS" at 12053.46,2667.77 h60
  text "TO MEET OR EXCEED THE REQUIREMENTS OF:" at 12053.46,2573.71 h60
  text "X" at 11690.97,2445.08 h60
  text "ANSI IPC-A-600F CLASS ->" at 11818.96,2445.08 h60
  text "X" at 13466.97,2445.08 h60
  text "2" at 13576.96,2445.08 h60
  text "1" at 13261.96,2443.58 h60
  text "3" at 13930.96,2443.58 h60
  text "X" at 12502.97,2297.39 h60
  text "RoHS" at 12630.96,2297.39 h60
  text "OTHER" at 13275.36,2297.39 h60
  text "PER ORDER" at 13672.42,2297.39 h60
  text "ALL BOARDS MUST MEET OR EXCEED UL94-V0 REQUIREMENTS." at 11356,2143.57 h60
  text "PCB MUST BEAR THE UL94V-0 UL REGISTERED MATERIAL ID NUMBER" at 11356,2027.5 h60
  text "ADDITIONAL REQUIREMENTS:" at 11328.46,1858.08 h60
  text "MICROSECTION:" at 11403.23,1750.95 h60
  text "YES" at 12308.96,1750.95 h60
  text "REQUIRED" at 13170.46,1606.62 h60
  text "BARE BOARD ELEC. TEST:" at 11403.23,1603.76 h60
  text "NONE" at 12708.96,1603.76 h60
  text "X" at 13052.46,1603.76 h60
  text "PER ORDER" at 13762.46,1603.76 h60
  text "XX MIL VIAS REQUIRE NON-CONDUCTIVE FILL AND PLANARIZE" at 11571.38,1398.82 h59
  text "XX MIL VIAS REQUIRE CONDUCTIVE FILL AND PLANARIZE" at 11579.38,1294.84 h60
  text "OUTER XX MIL VIAS REQUIRE 50 OHM SINGLE-ENDED IMPEDANCE" at 11578.39,1131.46 h58
  text "LAYER 2 & 3 (INNER LAYERS) XX MIL WIDE, XX MIL SPACE / TRACES REQUIRE 100 OHM DIFFERENTIAL IMPEDANCE" at 11570.39,895.74 h60
  text ".Layer_Name" at 577,-858.49 h60
M11 Gerber Information:
  lines w10: -292,-930.17 6308,-930.17 ; -292,-726.83 6310,-726.83 ; -292,-523.5 -292,-1133.5 3713,-1133.5 6310,-1133.5 6310,-523.5 -291.5,-523.5 -291.5,-1133.5 1284,-1133.5 ; 2173,-1133.5 2173,-523.5 ; 3440,-726.83 3440,-523.5 ; 4280,-726.83 4280,-523.5 ; 4902,-1140 4902,-937.17
  text "ALL ARTWORK VIEWED FROM TOP SIDE" at -228.5,-655.67 h60
  text "BOARD #:" at 2248,-655.67 h60
  text ".PRJ_Number" at 2793.5,-655.67 h60
  text "REV:" at 3638,-655.67 h60
  text ".PCB_Rev" at 3929.5,-655.67 h60
  text "SVN REV:" at 4476,-655.67 h60
  text ".VersionControl_RevNumber" at 4982,-655.67 h60
  text "LAYER NAME =" at -228.5,-858.49 h60
  text "PLOT NAME =" at -228.5,-1064.34 h60
  text ".plot_File_Name" at 577,-1064.34 h60
  text "GENERATED    :" at 2250,-1064.34 h60
  text ".Print_Date" at 3119.5,-1064.34 h60
  text ".Print_Time" at 3848.5,-1064.34 h60
  text "TEXAS INSTRUMENTS" at 5113,-1064.34 h60
M12 Stackup:
  drawing of 399 lines, arcs and shapes, not listed
  text "Layer" at 6796.2,7860 h60
  text "Name" at 7206.11,7860 h60
  text "Material" at 8135.85,7860 h60
  text "Thickness" at 8995.62,7860 h60
  text "Constant" at 9645.46,7860 h60
  text "Board Layer Stack" at 10215.32,7860 h60
  text "1" at 6796.2,7740 h60
  text "Top Overlay" at 7206.11,7740 h60
  text "2" at 6796.2,7620 h60
  text "Top Solder" at 7206.11,7620 h60
  text "Solder Resist" at 8135.85,7620 h60
  text "0.40mil" at 8995.62,7620 h60
  text "3.5" at 9645.46,7620 h60
  text "3" at 6796.2,7500 h60
  text "Top Layer" at 7206.11,7500 h60
  text "Copper" at 8135.85,7500 h60
  text "2.80mil" at 8995.62,7500 h60
  text "4" at 6796.2,7380 h60
  text "Dielectric1" at 7206.11,7380 h60
  text "FR-4" at 8135.85,7380 h60
  text "8.00mil" at 8995.62,7380 h60
  text "4.2" at 9645.46,7380 h60
  text "5" at 6796.2,7260 h60
  text "MidLayer1" at 7206.11,7260 h60
  text "Copper" at 8135.85,7260 h60
  text "2.80mil" at 8995.62,7260 h60
  text "6" at 6796.2,7140 h60
  text "Dielectric2" at 7206.11,7140 h60
  text "FR-4" at 8135.85,7140 h60
  text "10.00mil" at 8995.62,7140 h60
  text "4.8" at 9645.46,7140 h60
  text "7" at 6796.2,7020 h60
  text "MidLayer2" at 7206.11,7020 h60
  text "Copper" at 8135.85,7020 h60
  text "2.80mil" at 8995.62,7020 h60
  text "8" at 6796.2,6900 h60
  text "Dielectric3" at 7206.11,6900 h60
  text "FR-4" at 8135.85,6900 h60
  text "10.00mil" at 8995.62,6900 h60
  text "4.2" at 9645.46,6900 h60
  text "9" at 6796.2,6780 h60
  text "MidLayer3" at 7206.11,6780 h60
  text "Copper" at 8135.85,6780 h60
  text "2.80mil" at 8995.62,6780 h60
  text "10" at 6796.2,6660 h60
  text "Dielectric4" at 7206.11,6660 h60
  text "FR-4" at 8135.85,6660 h60
  text "10.00mil" at 8995.62,6660 h60
  text "4.8" at 9645.46,6660 h60
  text "11" at 6796.2,6540 h60
  text "MidLayer4" at 7206.11,6540 h60
  text "Copper" at 8135.85,6540 h60
  text "2.80mil" at 8995.62,6540 h60
  text "12" at 6796.2,6420 h60
  text "Dielectric5" at 7206.11,6420 h60
  text "FR-4" at 8135.85,6420 h60
  text "8.00mil" at 8995.62,6420 h60
  text "4.2" at 9645.46,6420 h60
  text "13" at 6796.2,6300 h60
  text "Bottom Layer" at 7206.11,6300 h60
  text "Copper" at 8135.85,6300 h60
  text "2.80mil" at 8995.62,6300 h60
  text "14" at 6796.2,6180 h60
  text "Bottom Solder" at 7206.11,6180 h60
  text "Solder Resist" at 8135.85,6180 h60
  text "0.40mil" at 8995.62,6180 h60
  text "3.5" at 9645.46,6180 h60
  text "15" at 6796.2,6060 h60
  text "Bottom Overlay" at 7206.11,6060 h60
  text ".Layer_Name" at 577,-858.49 h60
M13 Component Bodies Top:
  text ".Layer_Name" at 577,-858.49 h60
M14 Component Bodies Bottom:
  text ".Layer_Name" at 577,-858.49 h60
M15 Courtyards Top:
  text ".Layer_Name" at 577,-858.49 h60
M16 Courtyards Bottom:
  text ".Layer_Name" at 577,-858.49 h60
Drill Drawing:
  circle w10: c5183.72,2592.04 r27.63
  lines w10: 5156.09,2743.99 5211.34,2743.99 5183.72,2688.74 5156.09,2743.99 ; 5156.09,2813.06 5211.34,2813.06 5211.34,2868.31 5156.09,2868.31 5156.09,2813.06 ; 5156.09,2951.19 5169.9,2951.19 5183.72,2937.38 5197.53,2951.19 5211.34,2951.19 5197.53,2965 5211.34,2978.82 5197.53,2978.82 5183.72,2992.63 5169.9,2978.82 5156.09,2978.82 5169.9,2965 5156.09,2951.19 ; 5156.09,3061.7 5156.09,3075.51 5169.9,3089.32 5156.09,3103.14 5156.09,3116.95 5169.9,3116.95 5183.72,3103.14 5197.53,3116.95 5211.34,3116.95 5211.34,3103.14 5197.53,3089.32 5211.34,3075.51 5211.34,3061.7 5197.53,3061.7 5183.72,3075.51 5169.9,3061.7 5156.09,3061.7 ; 5156.09,3199.83 5169.9,3199.83 5169.9,3186.02 5197.53,3186.02 5197.53,3199.83 5211.34,3199.83 5211.34,3227.46 5197.53,3227.46 5197.53,3241.27 5169.9,3241.27 5169.9,3227.46 5156.09,3227.46 5156.09,3199.83 ; 5156.09,3310.34 5183.72,3324.15 5211.34,3310.34 5197.53,3337.96 5211.34,3365.59 5183.72,3351.78 5156.09,3365.59 5169.9,3337.96 5156.09,3310.34 ; 5156.09,3489.91 5211.34,3489.91 5183.72,3434.66 5156.09,3489.91 ; 5167.14,2732.94 5200.29,2732.94 5183.72,2699.79 5167.14,2732.94 ; 5167.14,2824.11 5200.29,2824.11 5200.29,2857.26 5167.14,2857.26 5167.14,2824.11 ; 5167.14,2956.71 5175.43,2956.71 5183.72,2948.43 5192.01,2956.71 5200.29,2956.71 5192.01,2965 5200.29,2973.29 5192.01,2973.29 5183.72,2981.58 5175.43,2973.29 5167.14,2973.29 5175.43,2965 5167.14,2956.71 ; 5167.14,3072.75 5167.14,3081.03 5175.43,3089.32 5167.14,3097.61 5167.14,3105.9 5175.43,3105.9 5183.72,3097.61 5192.01,3105.9 5200.29,3105.9 5200.29,3097.61 5192.01,3089.32 5200.29,3081.03 5200.29,3072.75 5192.01,3072.75 5183.72,3081.03 5175.43,3072.75 5167.14,3072.75 ; 5167.14,3205.35 5175.43,3205.35 5175.43,3197.07 5192.01,3197.07 5192.01,3205.35 5200.29,3205.35 5200.29,3221.93 5192.01,3221.93 5192.01,3230.22 5175.43,3230.22 5175.43,3221.93 5167.14,3221.93 5167.14,3205.35 ; 5167.14,3321.39 5183.72,3329.67 5200.29,3321.39 5192.01,3337.96 5200.29,3354.54 5183.72,3346.25 5167.14,3354.54 5175.43,3337.96 5167.14,3321.39
  lines w12: 5106,2527.12 8337.49,2527.12 ; 5106,3521.68 8337.49,3521.68 ; 5443.86,2402.8 5443.86,3646 ; 5775.86,2402.8 5775.86,3646 ; 6412.43,2402.8 6412.43,3646 ; 6671.57,2402.8 6671.57,3646 ; 7046.72,2402.8 7046.72,3646 ; 7771.05,2402.8 7771.05,3646 ; 5106,2402.8 8337.49,2402.8 8337.49,3646 5106,3646 5106,2402.8
  text "Symbol" at 5180.59,3558.98 h72
  text "Quantity" at 5481.16,3558.98 h72
  text "Finished Hole Size" at 5813.16,3558.98 h72
  text "Plated" at 6449.72,3558.98 h72
  text "Hole Type" at 6708.86,3558.98 h72
  text "Drill Layer Pair" at 7084.02,3558.98 h72
  text "Hole Tolerance" at 7808.35,3558.98 h72
  text "9" at 5481.16,3434.66 h60
  text "7.87mil (0.200mm)" at 5813.16,3434.66 h60
  text "PTH" at 6449.72,3434.66 h60
  text "Round" at 6708.86,3434.66 h60
  text "Top Layer - Bottom Layer" at 7084.02,3434.66 h60
  text "336" at 5481.16,3310.34 h60
  text "10.00mil (0.254mm)" at 5813.16,3310.34 h60
  text "PTH" at 6449.72,3310.34 h60
  text "Round" at 6708.86,3310.34 h60
  text "Top Layer - Bottom Layer" at 7084.02,3310.34 h60
  text "5" at 5481.16,3186.02 h60
  text "14.00mil (0.356mm)" at 5813.16,3186.02 h60
  text "PTH" at 6449.72,3186.02 h60
  text "Round" at 6708.86,3186.02 h60
  text "Top Layer - Bottom Layer" at 7084.02,3186.02 h60
  text "2" at 5481.16,3061.7 h60
  text "24.00mil (0.610mm)" at 5813.16,3061.7 h60
  text "PTH" at 6449.72,3061.7 h60
  text "Round" at 6708.86,3061.7 h60
  text "Top Layer - Bottom Layer" at 7084.02,3061.7 h60
  text "10" at 5481.16,2937.38 h60
  text "40.00mil (1.016mm)" at 5813.16,2937.38 h60
  text "PTH" at 6449.72,2937.38 h60
  text "Round" at 6708.86,2937.38 h60
  text "Top Layer - Bottom Layer" at 7084.02,2937.38 h60
  text "5" at 5481.16,2813.06 h60
  text "63.00mil (1.600mm)" at 5813.16,2813.06 h60
  text "PTH" at 6449.72,2813.06 h60
  text "Round" at 6708.86,2813.06 h60
  text "Top Layer - Bottom Layer" at 7084.02,2813.06 h60
  text "4" at 5481.16,2688.74 h60
  text "125.98mil (3.200mm)" at 5813.16,2688.74 h60
  text "PTH" at 6449.72,2688.74 h60
  text "Round" at 6708.86,2688.74 h60
  text "Top Layer - Bottom Layer" at 7084.02,2688.74 h60
  text "4" at 5481.16,2564.42 h60
  text "214.57mil (5.450mm)" at 5813.16,2564.42 h60
  text "PTH" at 6449.72,2564.42 h60
  text "Round" at 6708.86,2564.42 h60
  text "Top Layer - Bottom Layer" at 7084.02,2564.42 h60
  text "375 Total" at 5481.16,2440.1 h60
  text ".Layer_Name" at 577,-858.49 h60

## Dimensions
0,-410.5 to 1000,-410.5 on M2 Board Dimensions
0,0 to 3850,0 on M2 Board Dimensions
0,0 to 0,3650 on M2 Board Dimensions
